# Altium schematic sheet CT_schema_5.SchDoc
size 382 x 218 mm
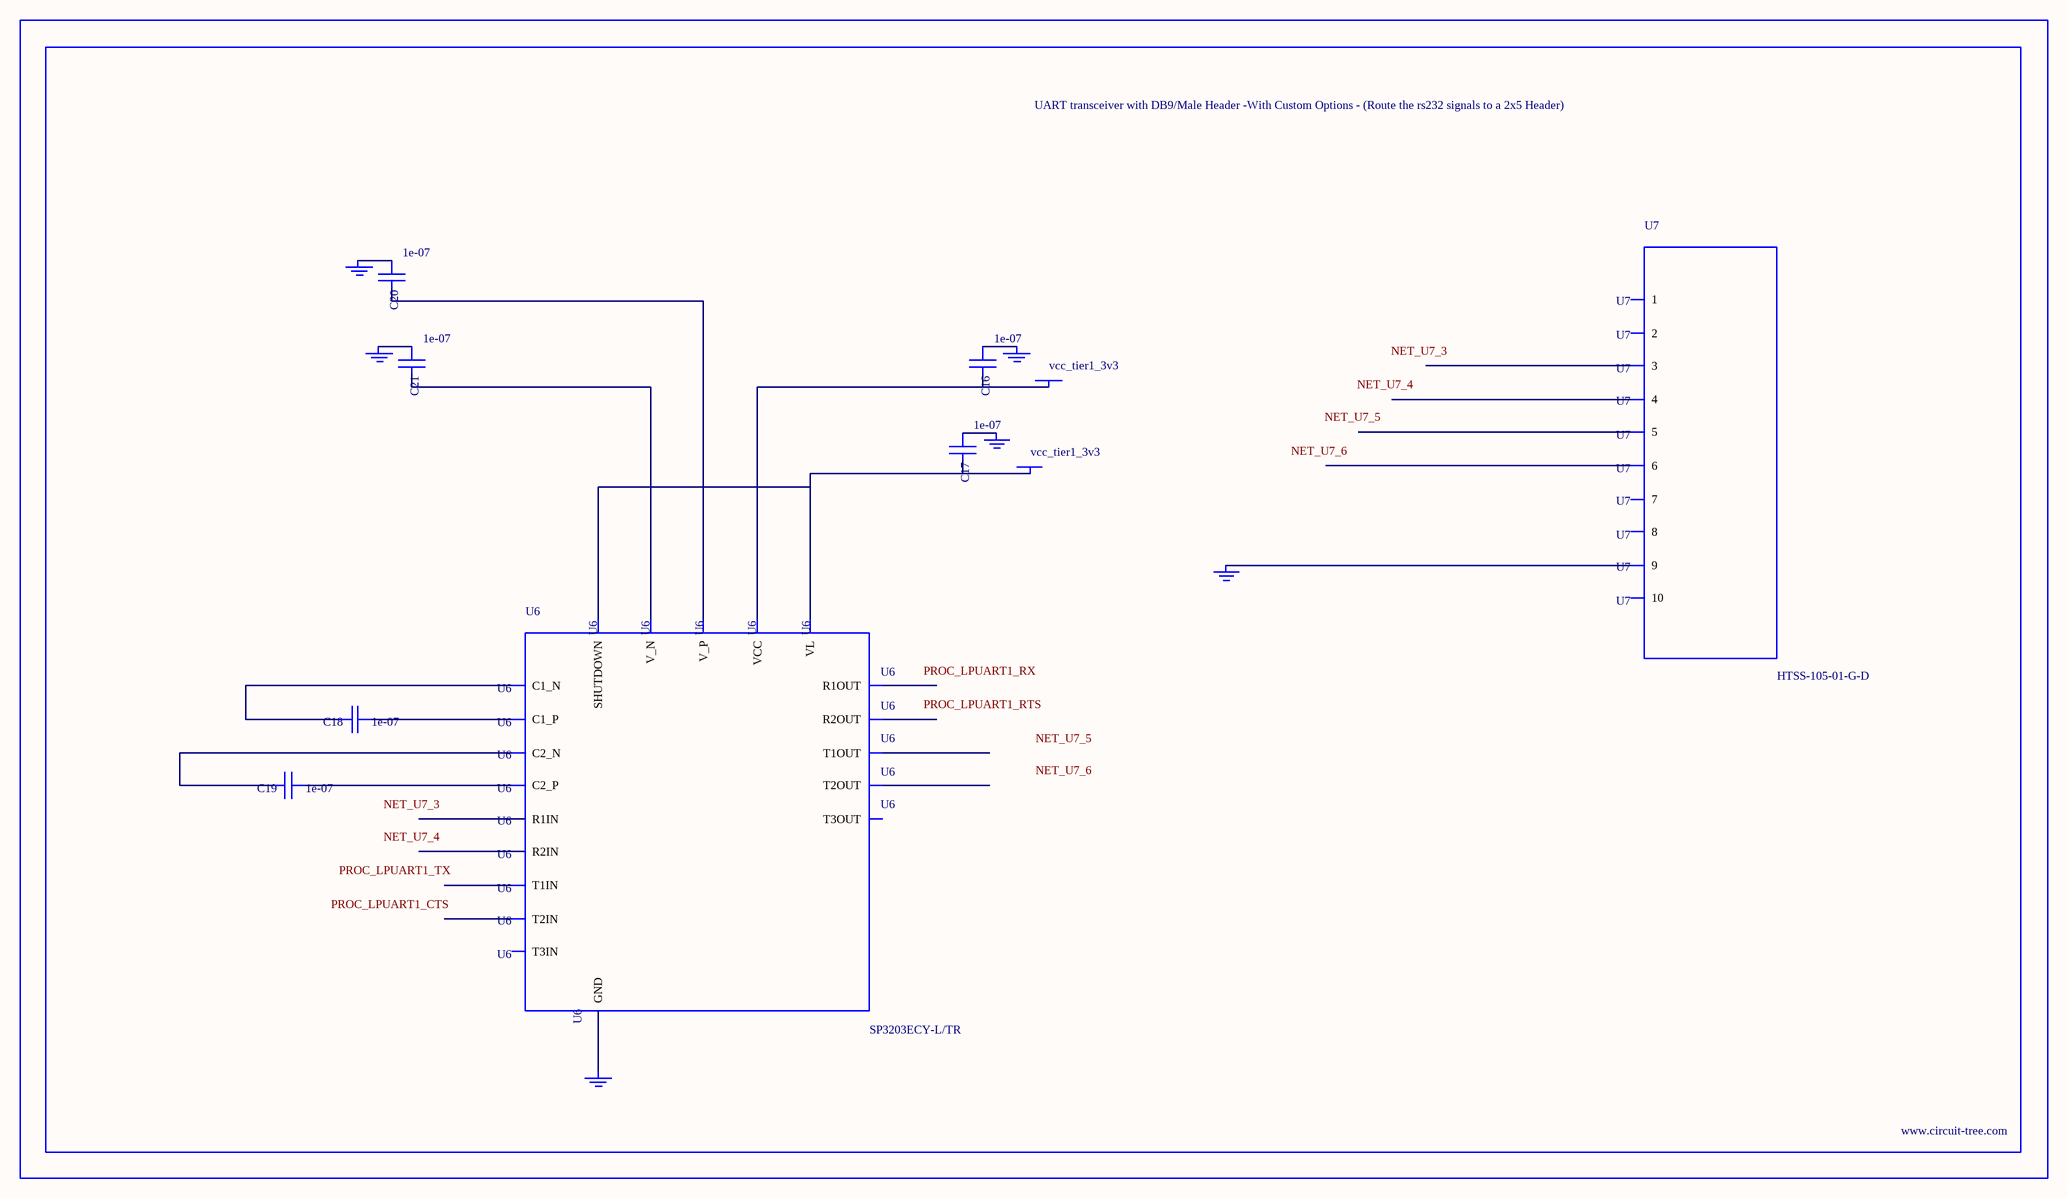
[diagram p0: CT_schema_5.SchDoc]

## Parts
BORDER4  (no value)
C16  1e-07  [C0402]
C17  1e-07  [C0402]
C18  1e-07  [C0402]
C19  1e-07  [C0402]
C20  1e-07  [C0402]
C21  1e-07  [C0402]
GND_INSTANCE_4_0  (no value)
GND_INSTANCE_4_1  (no value)
GND_INSTANCE_4_2  (no value)
GND_INSTANCE_4_3  (no value)
GND_INSTANCE_4_4  (no value)
GND_INSTANCE_4_5  (no value)
POWER_INSTANCE_4_0  vcc_tier1_3v3
POWER_INSTANCE_4_1  vcc_tier1_3v3
U6  SP3203ECY-L/TR  [TSSOP20-I]
U7  HTSS-105-01-G-D  [HTSS-105-01-G-D]

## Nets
NetC16_1: C16.1 GND_INSTANCE_4_3.0(GND)
NetC16_2: C16.2 POWER_INSTANCE_4_1.0(PWR) U6.19(VCC)
NetC17_1: C17.1 GND_INSTANCE_4_2.0(GND)
NetC17_2: C17.2 POWER_INSTANCE_4_0.0(PWR) U6.12(VL) U6.20(SHUTDOWN)
NetC18_1: C18.1 U6.1(C1_P)
NetC18_2: C18.2 U6.3(C1_N)
NetC19_1: C19.1 U6.4(C2_P)
NetC19_2: C19.2 U6.5(C2_N)
NetC20_1: C20.1 GND_INSTANCE_4_0.0(GND)
NetC20_2: C20.2 U6.2(V_P)
NetC21_1: C21.1 GND_INSTANCE_4_1.0(GND)
NetC21_2: C21.2 U6.6(V_N)
NetGND_INSTANCE_4_4_0: GND_INSTANCE_4_4.0(GND) U6.18(GND)
NetGND_INSTANCE_4_5_0: GND_INSTANCE_4_5.0(GND) U7.9

Not connected (* = marked no-connect by the designer): U6 7(T1IN) 8(T2IN) 9(T3IN) 10(R2OUT) 11(R1OUT) 13(R2IN) 14(R1IN) 15(T3OUT) 16(T2OUT) 17(T1OUT); U7 1 2 3 4 5 6 7 8 10

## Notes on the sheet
- Labels drawn without touching a wire or pin: NET_U7_3, NET_U7_4, NET_U7_5, NET_U7_6, PROC_LPUART1_CTS, PROC_LPUART1_RTS, PROC_LPUART1_RX, PROC_LPUART1_TX

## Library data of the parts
BORDER4 = BORDER_PAGE4
C16-C21 = C0402C104K3RACTU
GND_INSTANCE_4_0-GND_INSTANCE_4_5 = GND
POWER_INSTANCE_4_0 POWER_INSTANCE_4_1 = PWR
